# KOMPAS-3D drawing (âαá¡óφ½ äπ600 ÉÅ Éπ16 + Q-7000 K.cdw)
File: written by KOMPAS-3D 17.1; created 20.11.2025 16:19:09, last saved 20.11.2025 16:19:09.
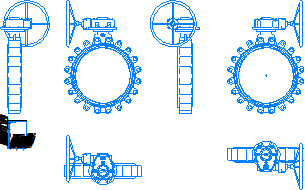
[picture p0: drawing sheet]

Sheet 1: A4, portrait

Title block, sheet 1: name: Сборка; material: Сталь 10  ГОСТ 1050-2013; mass: 315,48; sheets: 1; sheet format: A4

Views: Проекционный вид 2, Проекционный вид 3, Проекционный вид 5, Проекционный вид 6
Referenced files in \\adlc.lan\data\АДЛ_ПКД\3D-модели\ADL production\Дисковые поворотные затворы ГРАНВЭЛ\с резьбовыми проушинами с китайским редуктором Ру 16\KOMPAS 3D\: Гранвэл Ду600 РП Ру16 + Q-7000 K.m3d
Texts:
  Andrey
  АДЛ
Dimensions and other numbers on the sheet: 1:1; 1; 315,48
